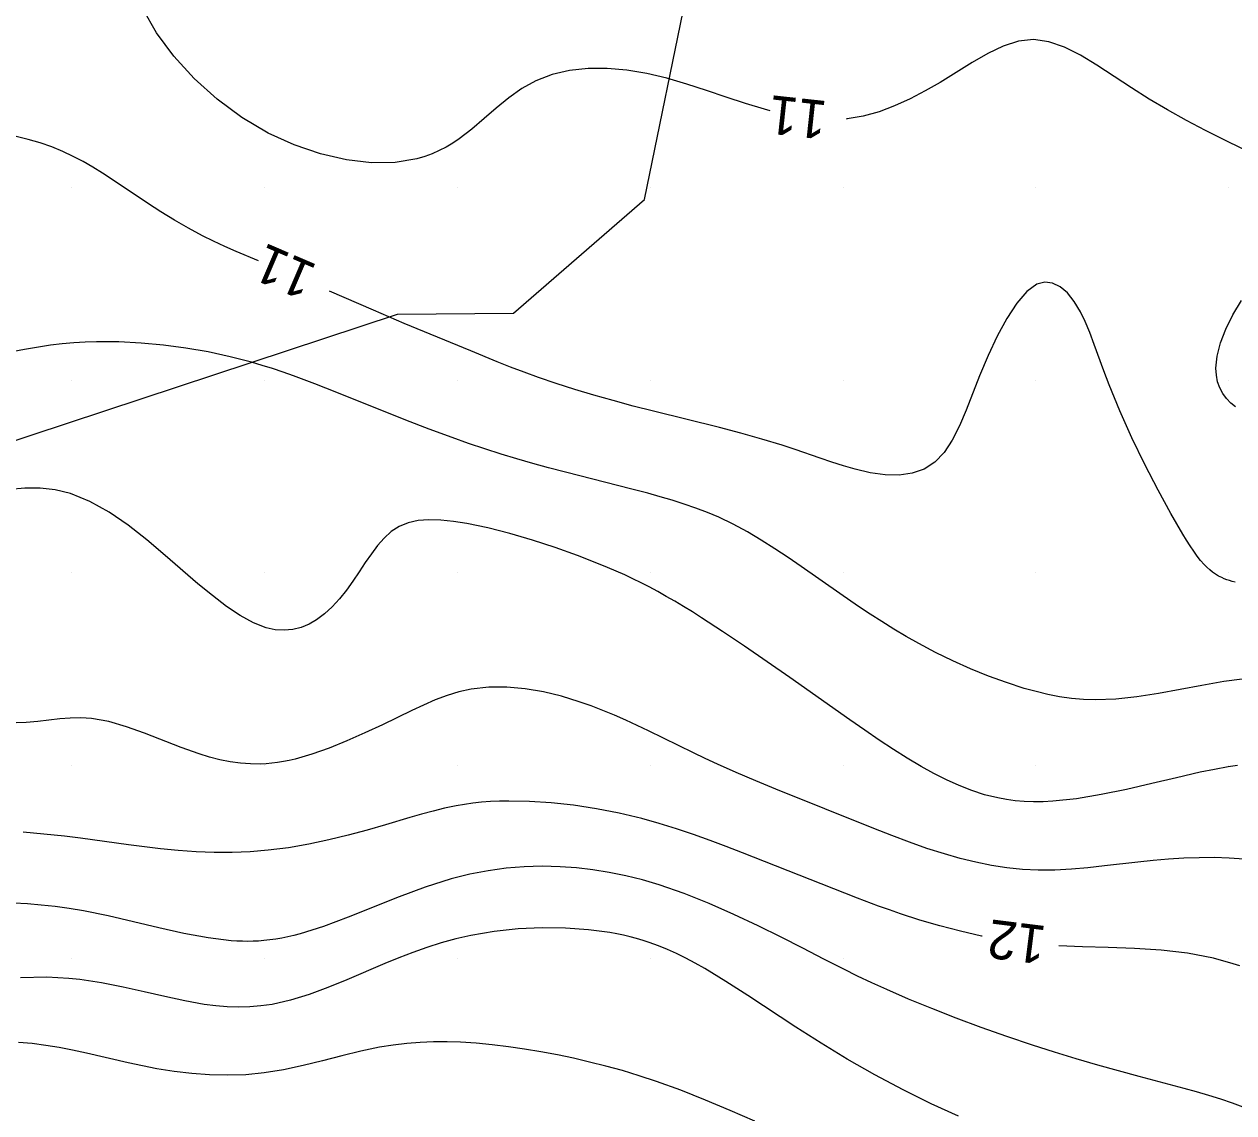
# Model space of a CAD drawing. Extents: x 2602990 to 2605851, y 618069 to 619180.
# Drawn here: x 2603217.5 to 2603280.3, y 618172 to 618228.5 of the extents above; entities that cross this region are included whole.
import ezdxf

# ---------------------------------------------------------------- set-up
doc = ezdxf.new("R2010")
doc.units = 0
for name, color, linetype in [('DTM Contours Major', 7, 'Continuous'), ('DTM Contours Major Text', 7, 'Continuous'), ('DTM Contours Minor', 7, 'Continuous'), ('DTM Contours Minor Text', 7, 'Continuous'), ('Exist DTM QL2 LIDAR Elevation Point', 7, 'Continuous'), ('PH Exist DTM Obscure Area', 7, 'Continuous')]:
    doc.layers.add(name, color=color, linetype=linetype)

msp = doc.modelspace()

# ---------------------------------------------------------------- linework, layer by layer
at = {"layer": 'DTM Contours Major'}
for points in [[(2603267.217, 618181.159), (2603267.183, 618181.166), (2603266.085, 618181.411), (2603265.013, 618181.69), (2603263.973, 618181.996), (2603262.969, 618182.321), (2603262.398, 618182.518), (2603261.838, 618182.719), (2603260.74, 618183.132), (2603258.863, 618183.867), (2603254.775, 618185.48), (2603253.943, 618185.803), (2603253.098, 618186.122), (2603252.238, 618186.434), (2603251.361, 618186.732), (2603250.468, 618187.01), (2603249.555, 618187.265), (2603248.387, 618187.542), (2603247.205, 618187.771), (2603246.024, 618187.95), (2603244.863, 618188.077), (2603243.737, 618188.151), (2603242.664, 618188.17), (2603242.181, 618188.16), (2603241.711, 618188.137), (2603241.252, 618188.101), (2603240.803, 618188.052), (2603240.36, 618187.99), (2603239.923, 618187.915), (2603239.327, 618187.79), (2603238.732, 618187.645), (2603238.133, 618187.483), (2603237.526, 618187.307), (2603236.271, 618186.934), (2603235.322, 618186.661), (2603234.337, 618186.397), (2603233.323, 618186.15), (2603232.288, 618185.93), (2603231.239, 618185.748), (2603230.183, 618185.613), (2603229.244, 618185.538), (2603228.308, 618185.503), (2603227.373, 618185.505), (2603226.443, 618185.54), (2603225.517, 618185.603), (2603224.596, 618185.69), (2603223.768, 618185.786), (2603222.943, 618185.894), (2603220.455, 618186.236), (2603219.613, 618186.34), (2603218.544, 618186.453), (2603217.467, 618186.551)], [(2603280.583, 618179.613), (2603280.059, 618179.784), (2603279.632, 618179.906), (2603279.203, 618180.015), (2603277.854, 618180.273), (2603276.488, 618180.433), (2603275.117, 618180.523), (2603273.753, 618180.573), (2603272.408, 618180.61), (2603271.182, 618180.661)]]:
    msp.add_lwpolyline(points, dxfattribs=at)
at = {"layer": 'DTM Contours Minor'}
for points in [[(2603256.21, 618223.971), (2603255.915, 618224.049), (2603254.932, 618224.35), (2603253.93, 618224.682), (2603252.914, 618225.025), (2603251.888, 618225.356), (2603250.857, 618225.656), (2603249.827, 618225.901), (2603248.789, 618226.077), (2603247.766, 618226.167), (2603246.771, 618226.165), (2603245.814, 618226.063), (2603244.906, 618225.852), (2603244.057, 618225.524), (2603243.336, 618225.12), (2603242.66, 618224.639), (2603242.012, 618224.111), (2603241.378, 618223.562), (2603240.743, 618223.023), (2603240.09, 618222.522), (2603239.757, 618222.296), (2603239.414, 618222.089), (2603239.058, 618221.901), (2603238.689, 618221.734), (2603238.303, 618221.591), (2603237.898, 618221.471), (2603236.772, 618221.286), (2603235.541, 618221.269), (2603234.236, 618221.418), (2603232.887, 618221.728), (2603231.526, 618222.195), (2603230.183, 618222.814), (2603228.815, 618223.625), (2603227.527, 618224.576), (2603226.344, 618225.641), (2603225.291, 618226.794), (2603224.393, 618228.009), (2603223.675, 618229.26)], [(2603280.718, 618222.003), (2603279.763, 618222.459), (2603278.788, 618222.95), (2603277.807, 618223.47), (2603276.832, 618224.015), (2603275.876, 618224.579), (2603274.952, 618225.156), (2603273.151, 618226.342), (2603272.304, 618226.857), (2603271.482, 618227.273), (2603270.678, 618227.553), (2603269.883, 618227.662), (2603269.093, 618227.577), (2603268.301, 618227.326), (2603267.503, 618226.947), (2603266.695, 618226.481), (2603265.034, 618225.444), (2603264.261, 618224.996), (2603263.474, 618224.584), (2603262.673, 618224.222), (2603261.862, 618223.92), (2603261.041, 618223.69), (2603260.215, 618223.545), (2603260.163, 618223.541)], [(2603229.677, 618216.186), (2603228.523, 618216.676), (2603227.931, 618216.938), (2603227.35, 618217.208), (2603226.78, 618217.49), (2603226.044, 618217.886), (2603225.323, 618218.303), (2603224.619, 618218.736), (2603223.929, 618219.178), (2603222.087, 618220.4), (2603221.587, 618220.725), (2603221.085, 618221.037), (2603220.579, 618221.332), (2603220.063, 618221.606), (2603219.534, 618221.856), (2603218.954, 618222.092), (2603218.355, 618222.299), (2603217.739, 618222.482), (2603217.107, 618222.643)], [(2603280.338, 618199.522), (2603280.187, 618199.559), (2603280.042, 618199.6), (2603279.902, 618199.646), (2603279.769, 618199.697), (2603279.64, 618199.754), (2603279.474, 618199.839), (2603279.314, 618199.935), (2603279.161, 618200.042), (2603279.012, 618200.162), (2603278.867, 618200.295), (2603278.725, 618200.441), (2603278.545, 618200.646), (2603278.367, 618200.874), (2603278.186, 618201.125), (2603278.002, 618201.4), (2603277.813, 618201.697), (2603277.617, 618202.017), (2603276.998, 618203.082), (2603276.333, 618204.3), (2603275.651, 618205.623), (2603274.981, 618207.006), (2603274.352, 618208.399), (2603273.793, 618209.757), (2603273.518, 618210.487), (2603273.028, 618211.846), (2603272.795, 618212.463), (2603272.558, 618213.032), (2603272.308, 618213.546), (2603271.983, 618214.083), (2603271.631, 618214.518), (2603271.258, 618214.84), (2603270.868, 618215.032), (2603270.466, 618215.081), (2603270.055, 618214.972), (2603269.53, 618214.596), (2603269.007, 618213.991), (2603268.493, 618213.203), (2603267.996, 618212.28), (2603267.523, 618211.269), (2603267.081, 618210.218), (2603266.382, 618208.439), (2603266.031, 618207.62), (2603265.656, 618206.882), (2603265.239, 618206.248), (2603264.762, 618205.745), (2603264.207, 618205.387), (2603263.583, 618205.171), (2603262.903, 618205.078), (2603262.175, 618205.093), (2603261.412, 618205.198), (2603260.624, 618205.376), (2603260.028, 618205.546), (2603259.422, 618205.739), (2603258.802, 618205.951), (2603257.516, 618206.399), (2603256.843, 618206.622), (2603255.793, 618206.941), (2603254.703, 618207.244), (2603253.583, 618207.535), (2603250.16, 618208.385), (2603249.11, 618208.656), (2603248.077, 618208.934), (2603247.065, 618209.22), (2603246.078, 618209.515), (2603245.12, 618209.82), (2603244.196, 618210.135), (2603243.461, 618210.404), (2603242.747, 618210.678), (2603242.05, 618210.956), (2603240.687, 618211.519), (2603237.237, 618212.943), (2603235.637, 618213.62), (2603233.353, 618214.61)], [(2603280.359, 618208.606), (2603280.116, 618208.804), (2603279.88, 618209.047), (2603279.687, 618209.314), (2603279.535, 618209.604), (2603279.426, 618209.917), (2603279.361, 618210.253), (2603279.34, 618210.612), (2603279.401, 618211.249), (2603279.572, 618211.933), (2603279.846, 618212.65), (2603280.212, 618213.387), (2603280.662, 618214.127)], [(2603280.69, 618194.494), (2603279.748, 618194.361), (2603278.613, 618194.168), (2603276.351, 618193.753), (2603275.239, 618193.578), (2603274.151, 618193.457), (2603273.095, 618193.413), (2603272.461, 618193.433), (2603271.839, 618193.489), (2603271.225, 618193.577), (2603270.616, 618193.696), (2603270.008, 618193.842), (2603269.399, 618194.013), (2603268.471, 618194.311), (2603267.539, 618194.653), (2603266.612, 618195.032), (2603265.696, 618195.443), (2603264.8, 618195.88), (2603263.933, 618196.337), (2603263.27, 618196.71), (2603262.627, 618197.09), (2603262.003, 618197.475), (2603261.397, 618197.865), (2603260.807, 618198.257), (2603259.826, 618198.931), (2603257.823, 618200.337), (2603257.15, 618200.799), (2603256.46, 618201.257), (2603255.756, 618201.702), (2603255.036, 618202.127), (2603254.302, 618202.523), (2603253.553, 618202.883), (2603252.963, 618203.134), (2603252.364, 618203.363), (2603251.756, 618203.573), (2603251.138, 618203.768), (2603250.51, 618203.952), (2603249.87, 618204.128), (2603249.045, 618204.347), (2603245.605, 618205.223), (2603244.721, 618205.457), (2603243.906, 618205.682), (2603243.086, 618205.918), (2603242.258, 618206.167), (2603241.421, 618206.432), (2603240.575, 618206.715), (2603239.717, 618207.016), (2603238.529, 618207.457), (2603237.328, 618207.925), (2603233.747, 618209.363), (2603232.594, 618209.813), (2603232.042, 618210.022), (2603231.495, 618210.222), (2603230.952, 618210.413), (2603230.409, 618210.595), (2603229.864, 618210.766), (2603229.313, 618210.928), (2603228.202, 618211.215), (2603227.067, 618211.459), (2603225.915, 618211.659), (2603224.755, 618211.813), (2603223.594, 618211.921), (2603222.44, 618211.982), (2603221.855, 618211.993), (2603221.271, 618211.991), (2603220.685, 618211.973), (2603220.094, 618211.938), (2603219.496, 618211.885), (2603218.888, 618211.812), (2603217.538, 618211.594), (2603216.164, 618211.334)], [(2603280.464, 618190.015), (2603279.973, 618189.939), (2603279.261, 618189.81), (2603278.522, 618189.658), (2603277.294, 618189.379), (2603276.009, 618189.075), (2603274.696, 618188.772), (2603273.385, 618188.5), (2603272.104, 618188.285), (2603270.884, 618188.154), (2603270.374, 618188.13), (2603269.879, 618188.128), (2603269.398, 618188.147), (2603268.928, 618188.187), (2603268.469, 618188.249), (2603268.017, 618188.332), (2603267.34, 618188.498), (2603266.674, 618188.711), (2603266.015, 618188.967), (2603265.358, 618189.263), (2603264.701, 618189.596), (2603264.04, 618189.963), (2603263.33, 618190.387), (2603262.608, 618190.842), (2603261.872, 618191.327), (2603261.12, 618191.838), (2603260.351, 618192.373), (2603257.237, 618194.569), (2603256.055, 618195.396), (2603254.886, 618196.201), (2603253.749, 618196.968), (2603252.662, 618197.676), (2603252.19, 618197.974), (2603251.73, 618198.257), (2603251.277, 618198.527), (2603250.83, 618198.785), (2603250.385, 618199.032), (2603249.939, 618199.27), (2603249.523, 618199.483), (2603249.101, 618199.69), (2603248.671, 618199.893), (2603248.231, 618200.091), (2603247.779, 618200.286), (2603247.313, 618200.479), (2603246.217, 618200.906), (2603245.066, 618201.316), (2603243.89, 618201.698), (2603242.716, 618202.04), (2603241.573, 618202.33), (2603240.489, 618202.557), (2603239.789, 618202.671), (2603239.131, 618202.74), (2603238.519, 618202.756), (2603237.953, 618202.712), (2603237.436, 618202.598), (2603236.968, 618202.406), (2603236.562, 618202.142), (2603236.195, 618201.809), (2603235.855, 618201.422), (2603235.533, 618200.992), (2603235.22, 618200.532), (2603234.904, 618200.057), (2603234.577, 618199.579), (2603234.237, 618199.11), (2603233.881, 618198.662), (2603233.506, 618198.246), (2603233.11, 618197.874), (2603232.693, 618197.559), (2603232.299, 618197.334), (2603231.886, 618197.167), (2603231.457, 618197.062), (2603231.011, 618197.022), (2603230.551, 618197.052), (2603230.077, 618197.153), (2603229.412, 618197.409), (2603228.724, 618197.785), (2603228.016, 618198.262), (2603227.288, 618198.82), (2603226.541, 618199.439), (2603224.846, 618200.91), (2603223.895, 618201.713), (2603222.925, 618202.473), (2603221.938, 618203.151), (2603220.937, 618203.711), (2603219.925, 618204.116), (2603219.141, 618204.303), (2603218.354, 618204.39), (2603217.566, 618204.392), (2603216.781, 618204.321)], [(2603280.793, 618185.155), (2603280.018, 618185.21), (2603279.243, 618185.234), (2603278.462, 618185.23), (2603277.675, 618185.202), (2603276.883, 618185.152), (2603276.087, 618185.084), (2603275.288, 618185.002), (2603273.564, 618184.799), (2603272.701, 618184.705), (2603271.838, 618184.63), (2603270.976, 618184.584), (2603270.117, 618184.58), (2603269.307, 618184.62), (2603268.499, 618184.704), (2603267.69, 618184.829), (2603266.881, 618184.992), (2603266.068, 618185.191), (2603265.251, 618185.423), (2603264.349, 618185.712), (2603263.44, 618186.031), (2603262.524, 618186.375), (2603261.599, 618186.737), (2603256.519, 618188.785), (2603255.475, 618189.217), (2603254.459, 618189.649), (2603253.482, 618190.083), (2603252.853, 618190.374), (2603252.241, 618190.664), (2603249.906, 618191.803), (2603249.322, 618192.083), (2603248.735, 618192.355), (2603248.144, 618192.617), (2603247.544, 618192.867), (2603246.934, 618193.102), (2603246.31, 618193.322), (2603245.394, 618193.6), (2603244.456, 618193.828), (2603243.507, 618193.991), (2603242.559, 618194.078), (2603241.622, 618194.075), (2603240.707, 618193.97), (2603240.077, 618193.829), (2603239.459, 618193.639), (2603238.847, 618193.409), (2603238.238, 618193.147), (2603237.625, 618192.862), (2603236.105, 618192.128), (2603235.189, 618191.699), (2603234.268, 618191.289), (2603233.352, 618190.916), (2603232.45, 618190.596), (2603231.573, 618190.344), (2603231.269, 618190.274), (2603230.968, 618190.214), (2603230.67, 618190.166), (2603230.375, 618190.129), (2603230.081, 618190.103), (2603229.789, 618190.088), (2603229.264, 618190.092), (2603228.738, 618190.132), (2603228.211, 618190.206), (2603227.68, 618190.312), (2603227.143, 618190.448), (2603226.599, 618190.613), (2603225.667, 618190.945), (2603223.771, 618191.686), (2603222.83, 618192.024), (2603221.909, 618192.291), (2603221.019, 618192.451), (2603220.462, 618192.484), (2603219.915, 618192.472), (2603219.367, 618192.427), (2603218.233, 618192.301), (2603217.628, 618192.247), (2603216.589, 618192.21)], [(2603281.026, 618172.182), (2603280.201, 618172.497), (2603279.584, 618172.708), (2603278.962, 618172.903), (2603278.332, 618173.087), (2603277.692, 618173.263), (2603275.349, 618173.884), (2603274.292, 618174.17), (2603273.206, 618174.474), (2603272.096, 618174.797), (2603270.966, 618175.139), (2603269.822, 618175.503), (2603268.489, 618175.952), (2603267.163, 618176.423), (2603265.86, 618176.91), (2603264.599, 618177.405), (2603263.397, 618177.899), (2603262.271, 618178.387), (2603261.495, 618178.739), (2603260.754, 618179.089), (2603260.032, 618179.444), (2603258.995, 618179.971), (2603257.912, 618180.529), (2603256.785, 618181.104), (2603255.586, 618181.696), (2603254.335, 618182.284), (2603253.051, 618182.848), (2603251.752, 618183.366), (2603250.459, 618183.816), (2603249.588, 618184.074), (2603248.726, 618184.291), (2603247.871, 618184.468), (2603247.019, 618184.606), (2603246.168, 618184.704), (2603245.317, 618184.764), (2603244.394, 618184.785), (2603243.466, 618184.758), (2603242.531, 618184.682), (2603241.588, 618184.554), (2603240.636, 618184.369), (2603239.672, 618184.126), (2603238.331, 618183.701), (2603236.983, 618183.201), (2603234.328, 618182.144), (2603233.053, 618181.668), (2603231.835, 618181.282), (2603231.514, 618181.197), (2603231.197, 618181.123), (2603230.884, 618181.059), (2603230.573, 618181.004), (2603230.264, 618180.961), (2603229.955, 618180.928), (2603229.679, 618180.907), (2603229.403, 618180.895), (2603229.124, 618180.891), (2603228.843, 618180.895), (2603228.558, 618180.907), (2603228.27, 618180.926), (2603227.065, 618181.072), (2603225.804, 618181.305), (2603224.507, 618181.593), (2603223.194, 618181.904), (2603221.883, 618182.207), (2603220.595, 618182.47), (2603219.857, 618182.594), (2603219.13, 618182.694), (2603218.411, 618182.773), (2603217.699, 618182.83), (2603216.99, 618182.869)], [(2603265.986, 618171.815), (2603264.564, 618172.469), (2603263.113, 618173.186), (2603261.654, 618173.96), (2603260.209, 618174.783), (2603258.857, 618175.607), (2603257.544, 618176.446), (2603255.064, 618178.074), (2603253.91, 618178.815), (2603252.825, 618179.476), (2603252.326, 618179.76), (2603251.84, 618180.02), (2603251.364, 618180.257), (2603250.893, 618180.472), (2603250.422, 618180.666), (2603249.949, 618180.838), (2603249.622, 618180.943), (2603249.291, 618181.039), (2603248.955, 618181.127), (2603248.611, 618181.207), (2603248.259, 618181.278), (2603247.898, 618181.342), (2603246.787, 618181.489), (2603245.61, 618181.573), (2603244.388, 618181.59), (2603243.145, 618181.536), (2603241.903, 618181.406), (2603240.685, 618181.198), (2603239.913, 618181.018), (2603239.157, 618180.808), (2603238.414, 618180.57), (2603237.683, 618180.31), (2603236.958, 618180.03), (2603236.237, 618179.736), (2603234.258, 618178.896), (2603233.275, 618178.496), (2603232.301, 618178.137), (2603231.337, 618177.839), (2603230.385, 618177.623), (2603229.802, 618177.538), (2603229.221, 618177.49), (2603228.64, 618177.476), (2603228.056, 618177.495), (2603227.467, 618177.544), (2603226.868, 618177.621), (2603225.857, 618177.801), (2603224.817, 618178.028), (2603223.749, 618178.276), (2603222.657, 618178.522), (2603221.542, 618178.741), (2603220.406, 618178.909), (2603219.842, 618178.966), (2603219.272, 618179.005), (2603218.695, 618179.025), (2603217.337, 618179.003)], [(2603255.421, 618171.561), (2603254.148, 618172.116), (2603252.863, 618172.656), (2603251.58, 618173.166), (2603250.314, 618173.628), (2603249.429, 618173.921), (2603248.557, 618174.184), (2603247.698, 618174.42), (2603246.851, 618174.633), (2603246.014, 618174.824), (2603245.186, 618174.997), (2603244.328, 618175.16), (2603243.479, 618175.305), (2603242.637, 618175.428), (2603241.802, 618175.529), (2603240.974, 618175.606), (2603240.152, 618175.656), (2603239.457, 618175.676), (2603238.764, 618175.674), (2603238.07, 618175.647), (2603237.373, 618175.594), (2603236.671, 618175.511), (2603235.961, 618175.396), (2603234.991, 618175.194), (2603234.005, 618174.954), (2603233.006, 618174.699), (2603231.998, 618174.451), (2603230.984, 618174.232), (2603229.966, 618174.067), (2603229.022, 618173.976), (2603228.081, 618173.944), (2603227.146, 618173.965), (2603226.221, 618174.032), (2603225.308, 618174.14), (2603224.411, 618174.283), (2603223.662, 618174.427), (2603222.924, 618174.586), (2603220.752, 618175.089), (2603220.033, 618175.244), (2603219.342, 618175.378), (2603218.646, 618175.492), (2603217.943, 618175.585), (2603217.23, 618175.652)]]:
    msp.add_lwpolyline(points, dxfattribs=at)
at = {"layer": 'Exist DTM QL2 LIDAR Elevation Point'}
for p, q in [((2603220, 618220), (2603220, 618220)), ((2603230, 618220), (2603230, 618220)), ((2603240, 618220), (2603240, 618220)), ((2603250, 618220), (2603250, 618220)), ((2603260, 618220), (2603260, 618220)), ((2603270, 618220), (2603270, 618220)), ((2603280, 618220), (2603280, 618220)), ((2603220, 618210), (2603220, 618210)), ((2603230, 618210), (2603230, 618210)), ((2603240, 618210), (2603240, 618210)), ((2603250, 618210), (2603250, 618210)), ((2603260, 618210), (2603260, 618210)), ((2603270, 618210), (2603270, 618210)), ((2603280, 618210), (2603280, 618210)), ((2603220, 618200), (2603220, 618200)), ((2603230, 618200), (2603230, 618200)), ((2603240, 618200), (2603240, 618200)), ((2603250, 618200), (2603250, 618200)), ((2603260, 618200), (2603260, 618200)), ((2603270, 618200), (2603270, 618200)), ((2603280, 618200), (2603280, 618200)), ((2603220, 618190), (2603220, 618190)), ((2603230, 618190), (2603230, 618190)), ((2603240, 618190), (2603240, 618190)), ((2603250, 618190), (2603250, 618190)), ((2603260, 618190), (2603260, 618190)), ((2603270, 618190), (2603270, 618190)), ((2603280, 618190), (2603280, 618190)), ((2603220, 618180), (2603220, 618180)), ((2603230, 618180), (2603230, 618180)), ((2603240, 618180), (2603240, 618180)), ((2603250, 618180), (2603250, 618180)), ((2603260, 618180), (2603260, 618180)), ((2603270, 618180), (2603270, 618180)), ((2603280, 618180), (2603280, 618180))]:
    msp.add_line(p, q, dxfattribs=at)
at = {"layer": 'PH Exist DTM Obscure Area'}
msp.add_lwpolyline([(2603214.095, 618205.908), (2603236.88, 618213.413), (2603242.897, 618213.478), (2603249.693, 618219.367), (2603251.965, 618230.407), (2603242.886, 618234.25), (2603237.813, 618233.008), (2603228.59, 618230.749), (2603221.465, 618233.662), (2603224.846, 618242.398), (2603230.879, 618251.696), (2603237.516, 618266.865), (2603238.005, 618272.966), (2603243.908, 618279.156), (2603247.154, 618283.746), (2603250.298, 618290.986), (2603258.623, 618297.971), (2603270.971, 618303.439), (2603273.862, 618305.958), (2603281.14, 618310.76)], dxfattribs=at)

# ---------------------------------------------------------------- texts
at = {"layer": 'DTM Contours Major Text'}
msp.add_text('12', height=2, rotation=172.83359, dxfattribs=at).set_placement((2603270.604, 618181.667))
at = {"layer": 'DTM Contours Minor Text'}
for rotation, p in [(173.80422, (2603259.23, 618224.459)), (156.78896, (2603232.794, 618215.945))]:
    msp.add_text('11', height=2, rotation=rotation, dxfattribs=at).set_placement(p)

doc.saveas('drawing.dxf')
